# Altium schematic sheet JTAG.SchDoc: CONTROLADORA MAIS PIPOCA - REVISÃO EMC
size A3; DocumentNumber: GA0050; SheetNumber: 13; SheetTotal: 17
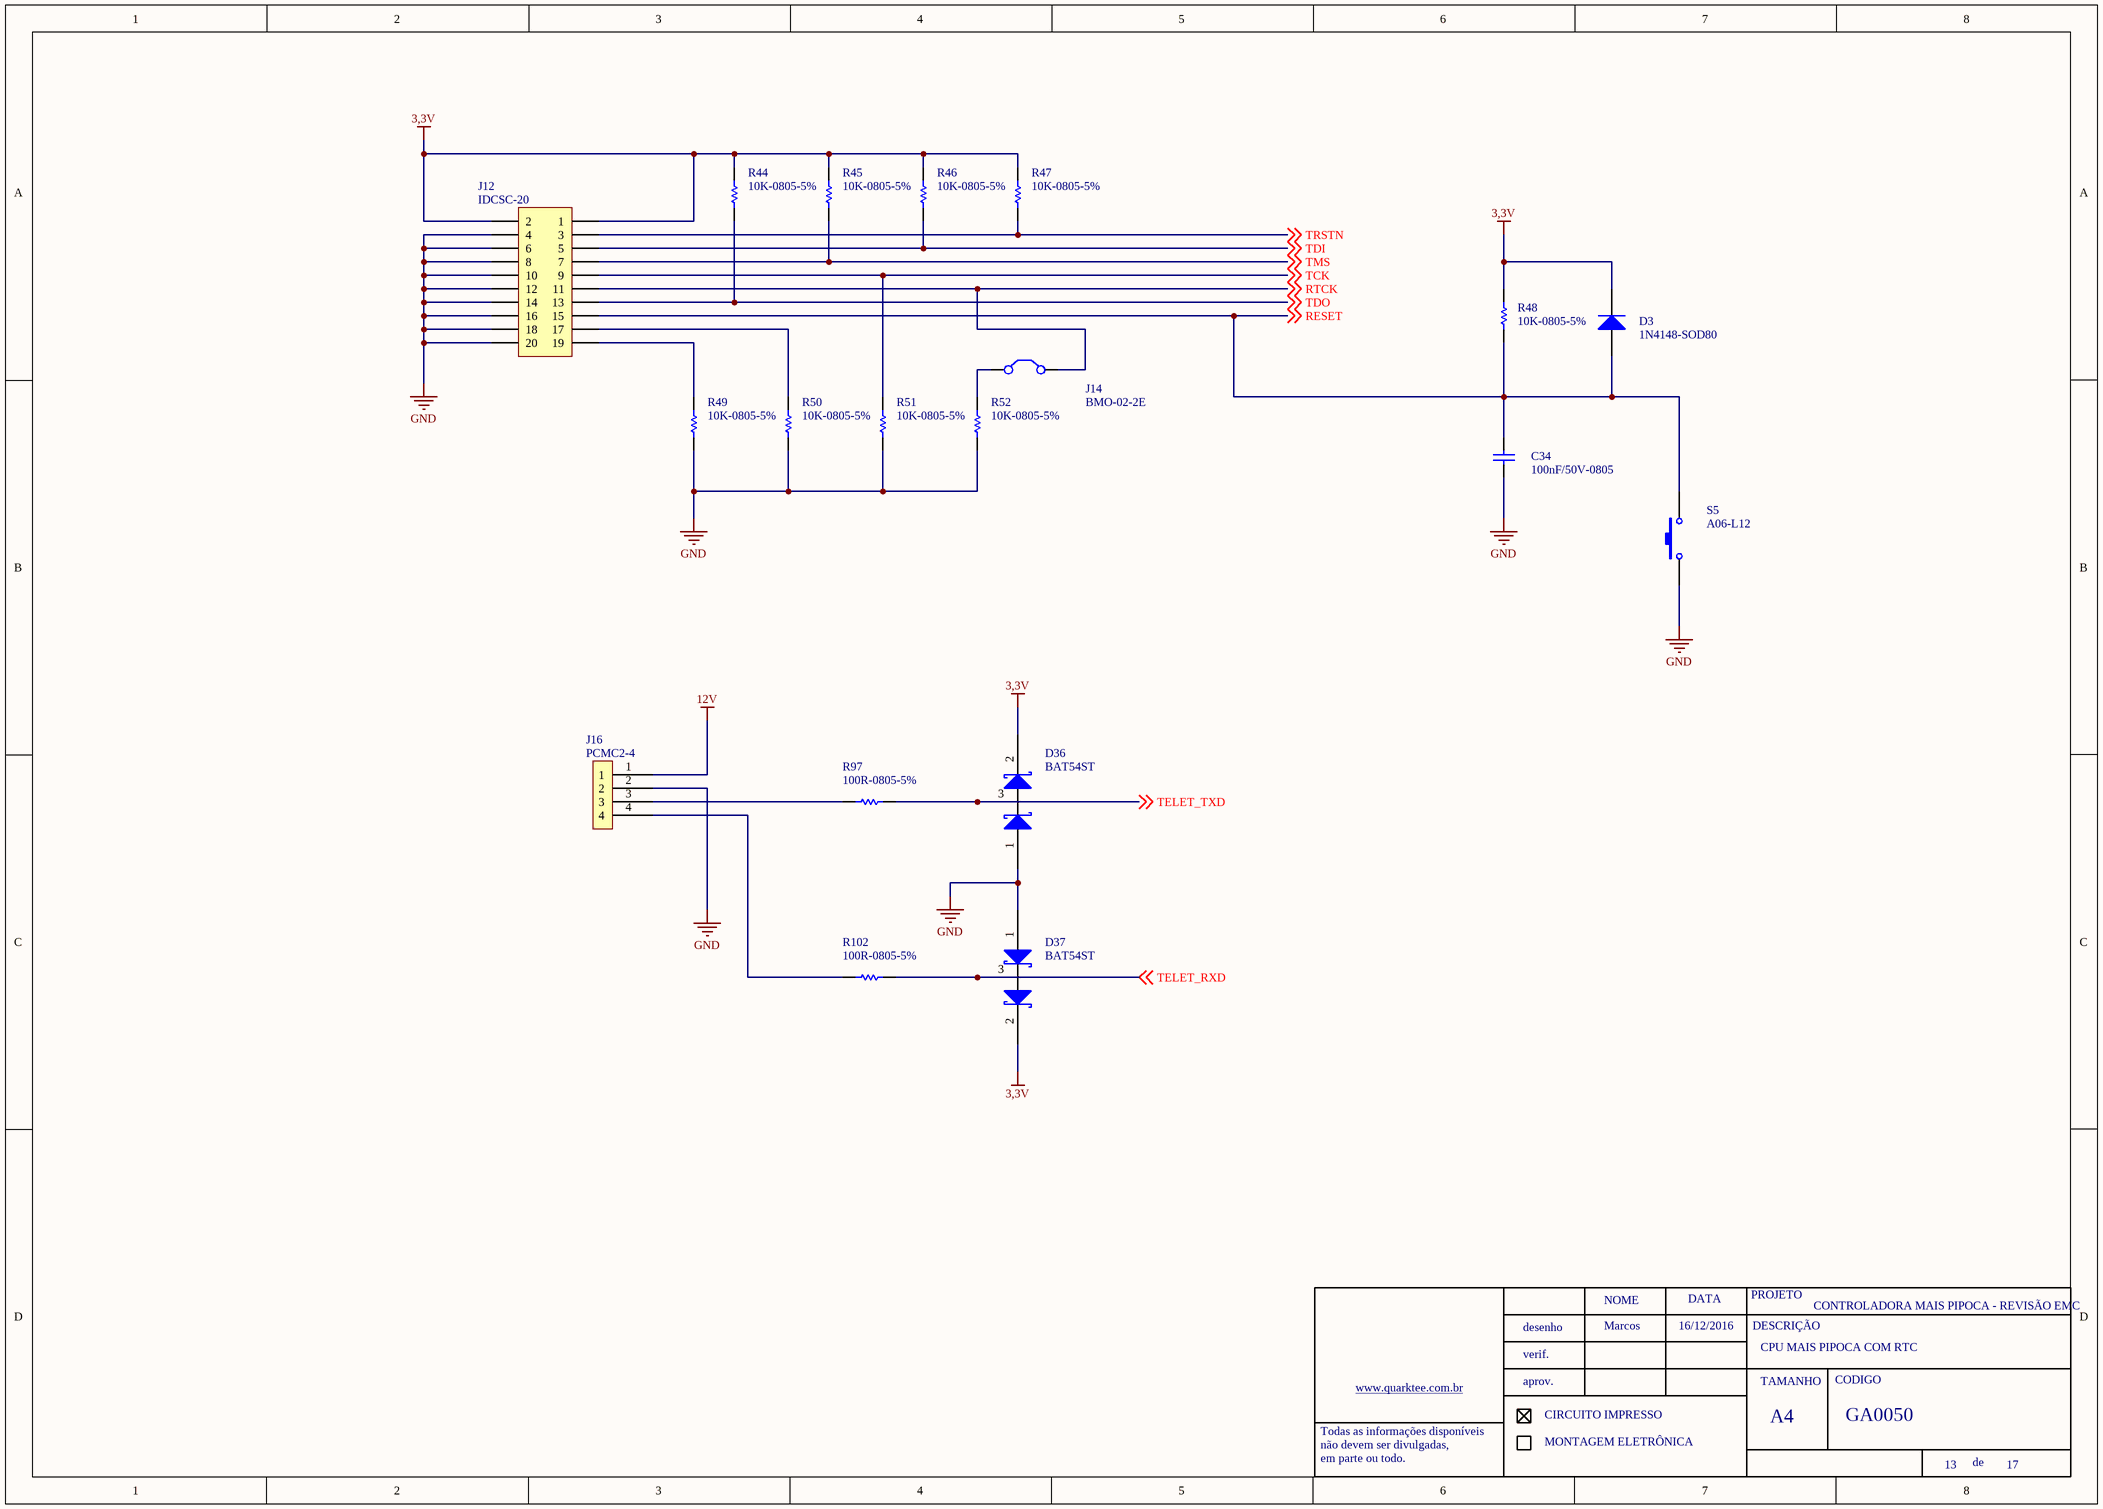
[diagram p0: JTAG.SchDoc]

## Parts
C34  100nF/50V-0805  [0805-REVISADO ONDA]
D3  1N4148-SOD80  [MINIMLEF/SOD80 - REVISADO ONDA]
D36  BAT54ST  [SOT23 - REVISADO ONDA]
D37  BAT54ST  [SOT23 - REVISADO ONDA]
J12  IDCSC-20  [IDCSC-20]
J14  BMO-02-2E  [JUMPER100]
J16  PCMC2-4  [PHMC4-04]
R44  10K-0805-5%  [0805-REVISADO ONDA]
R45  10K-0805-5%  [0805-REVISADO ONDA]
R46  10K-0805-5%  [0805-REVISADO ONDA]
R47  10K-0805-5%  [0805-REVISADO ONDA]
R48  10K-0805-5%  [0805-REVISADO ONDA]
R49  10K-0805-5%  [0805-REVISADO ONDA]
R50  10K-0805-5%  [0805-REVISADO ONDA]
R51  10K-0805-5%  [0805-REVISADO ONDA]
R52  10K-0805-5%  [0805-REVISADO ONDA]
R97  100R-0805-5%  [0805-REVISADO ONDA]
R102  100R-0805-5%  [0805-REVISADO ONDA]
S5  A06-L12  [CHAVE_A06]

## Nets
3,3V: D3.2 D36.2 D37.2 J12.1 J12.2 R44.1 R45.1 R46.1 R47.1 R48.2
12V: J16.1
GND: C34.1 D36.1 D37.1 J12.4 J12.6 J12.8 J12.10 J12.12 J12.14 J12.16 J12.18 J12.20 J16.2 R49.2 R50.2 R51.2 R52.2 S5.1
RESET: C34.2 D3.1 J12.15 R48.1 S5.2 ; off-sheet RESET
RTCK: J12.11 J14.2(C2) ; off-sheet RTCK
TCK: J12.9 R51.1 ; off-sheet TCK
TDI: J12.5 R46.2 ; off-sheet TDI
TDO: J12.13 R44.2 ; off-sheet TDO
TELET_RXD: D37.3 R102.2 ; off-sheet TELET_RXD
TELET_TXD: D36.3 R97.2 ; off-sheet TELET_TXD
TMS: J12.7 R45.2 ; off-sheet TMS
TRSTN: J12.3 R47.2 ; off-sheet TRSTN
NetJ12_17: J12.17 R50.1
NetJ12_19: J12.19 R49.1
NetJ14_1: J14.1(C1) R52.1
NetJ16_3: J16.3 R97.1
NetJ16_4: J16.4 R102.1

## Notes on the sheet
- Marcos
- 16/12/2016
- CPU MAIS PIPOCA COM RTC

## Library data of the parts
C34 = 100nF/50-0805-NPO
J12 = HEADER 10x2: BARRA DE PINOS 10x2 VIAS; ERP: 10 x 434.00.060
J14 = BARRA DE PINOS
R44-R47 R49-R52 = RES 10K-0805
